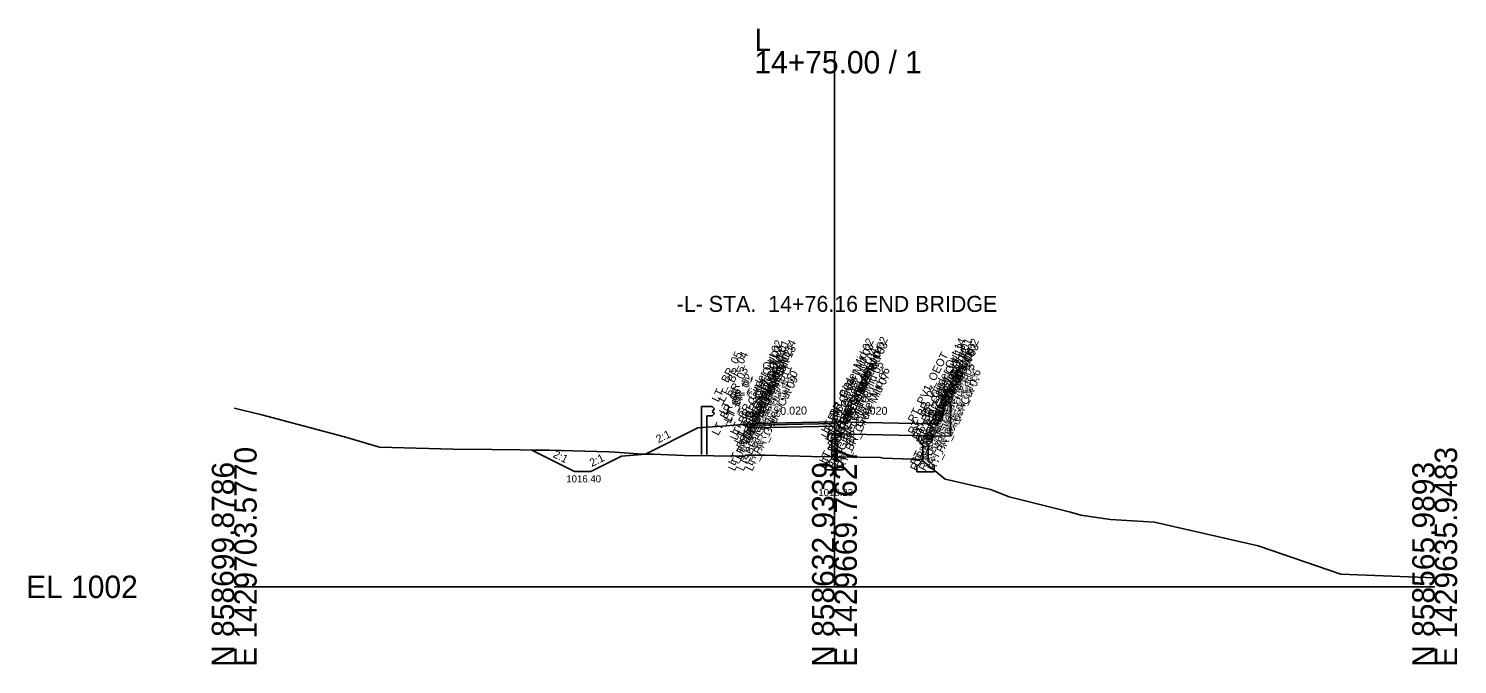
# Model space of a CAD drawing. Extents: x -26 to 153, y -10 to 13058.
# Drawn here: x -25.7 to 152.8, y 6490.3 to 6569.7 of the extents above; entities that cross this region are included whole.
import ezdxf

# ---------------------------------------------------------------- set-up
doc = ezdxf.new("R2010")
doc.units = 0
for name, color, linetype in [('Default', 7, 'Continuous'), ('Exist Cross Section Cell', 7, 'Continuous'), ('Exist XS Ground Line', 7, 'Continuous'), ('Old_Level_50', 7, 'Continuous'), ('Prop CMT Concrete Structures', 7, 'Continuous'), ('Prop CMT Ditch DDE', 7, 'Continuous'), ('Prop CMT Guardrail Graphics', 7, 'Continuous'), ('Prop CMT Pvmt Course 1', 7, 'Continuous'), ('Prop CMT Pvmt Course 2', 7, 'Continuous'), ('Prop CMT Pvmt Surface', 7, 'Continuous'), ('Prop CMT Pvmt Surface Shoulder', 7, 'Continuous'), ('Prop CMT Shld Paved Course 1', 7, 'Continuous'), ('Prop CMT Shld Paved Course 2', 7, 'Continuous'), ('Prop CMT Slope Grass', 7, 'Continuous'), ('Prop CMT Subgrade Daylight Point', 7, 'Continuous'), ('Prop CMT Subgrade Earthwork', 7, 'Continuous'), ('Prop XS Dump Level', 7, 'Continuous'), ('Prop XS SE Text', 7, 'Continuous'), ('Prop XS Side Slope Text', 7, 'Continuous'), ('Prop XSC Text', 7, 'Continuous')]:
    doc.layers.add(name, color=color, linetype=linetype)

msp = doc.modelspace()

# ---------------------------------------------------------------- linework, layer by layer
at = {"layer": 'Exist Cross Section Cell'}
for p, q in [((75, 6500), (75, 6566.93)), ((0, 6500), (75, 6500)), ((75, 6500), (150, 6500))]:
    msp.add_line(p, q, dxfattribs=at)
at = {"layer": 'Exist XS Ground Line'}
msp.add_lwpolyline([(0, 6522.31), (3.44, 6521.49), (13.79, 6518.72), (18.17, 6517.45), (27.35, 6517.18), (32.2, 6517.15), (39.36, 6517.05), (46.79, 6516.88), (47.56, 6516.84), (51.03, 6516.57), (52.33, 6516.56), (56.24, 6516.42), (59.9, 6516.38), (62.96, 6516.34), (63.78, 6516.33), (63.92, 6516.46), (66.35, 6516.43), (72.14, 6516.29), (75, 6516.23), (75.38, 6516.22), (80.77, 6516.15), (81.07, 6516.09), (85.84, 6515.89), (88.82, 6513.45), (94.51, 6512.15), (96.84, 6511.22), (104.48, 6509.34), (105.79, 6508.93), (109.51, 6508.39), (114.97, 6508.07), (127.95, 6505.12), (138.29, 6501.59), (146.77, 6501.25), (150, 6501.11)], dxfattribs=at)
at = {"layer": 'Old_Level_50'}
for p, q in [((37.18, 6517.08), (42.54, 6514.4)), ((48.39, 6516.33), (51.39, 6516.57)), ((51.39, 6516.57), (51.03, 6516.57)), ((44.54, 6514.4), (48.39, 6516.33)), ((42.54, 6514.4), (44.54, 6514.4))]:
    msp.add_line(p, q, dxfattribs=at)
msp.add_lwpolyline([(51.03, 6516.57), (47.56, 6516.84), (46.79, 6516.88), (39.36, 6517.05), (37.18, 6517.08)], dxfattribs=at)
at = {"layer": 'Prop CMT Concrete Structures'}
for points in [[(75, 6520.61), (85, 6520.41), (88, 6520.35), (88.01, 6520.6), (88.59, 6521.43), (88.76, 6523.01), (89.5, 6523.01), (89.5, 6518.82)], [(75, 6519.11), (75, 6520.61)], [(75, 6519.11), (75, 6520.61)], [(75, 6519.11), (74.17, 6519.09)], [(74.17, 6519.09), (74.17, 6518.44)], [(74.17, 6518.44), (74.67, 6517.94)], [(75, 6514.61), (75, 6519.11)], [(75, 6519.11), (75.83, 6519.09)], [(75, 6514.61), (75, 6519.11)], [(89.5, 6518.82), (85, 6518.91), (75, 6519.11)], [(75.83, 6518.44), (75.33, 6517.94)], [(75.83, 6519.09), (75.83, 6518.44)], [(85.54, 6518.9), (86.38, 6518.88), (87.21, 6518.86)], [(85.54, 6518.21), (85.54, 6518.9)], [(87.21, 6518.86), (87.21, 6518.21)], [(74.67, 6517.94), (74.67, 6516.02)], [(75.33, 6517.94), (75.33, 6516.02)], [(86.04, 6517.71), (85.54, 6518.21)], [(86.04, 6515.8), (86.04, 6517.71)], [(87.21, 6518.21), (86.71, 6517.71)], [(86.71, 6517.71), (86.71, 6515.8)], [(74.67, 6516.02), (73.92, 6515.27)], [(73.92, 6515.27), (73.92, 6514.61)], [(75.33, 6516.02), (76.08, 6515.27)], [(76.08, 6515.27), (76.08, 6514.61)], [(85.29, 6515.05), (86.04, 6515.8)], [(85.29, 6514.38), (85.29, 6515.05)], [(86.71, 6515.8), (87.46, 6515.05)], [(87.46, 6515.05), (87.46, 6514.38)], [(73.92, 6514.61), (75, 6514.61)], [(76.08, 6514.61), (75, 6514.61)], [(87.46, 6514.38), (86.38, 6514.38), (85.29, 6514.38)]]:
    msp.add_lwpolyline(points, dxfattribs=at)
at = {"layer": 'Prop CMT Ditch DDE'}
for p, q in [((42.54, 6514.4), (37.18, 6517.08)), ((51.39, 6516.57), (48.39, 6516.33)), ((44.54, 6514.4), (48.39, 6516.33)), ((44.54, 6514.4), (42.54, 6514.4))]:
    msp.add_line(p, q, dxfattribs=at)
at = {"layer": 'Prop CMT Guardrail Graphics'}
for points in [[(58.4, 6516.51), (58.4, 6522.51)], [(58.4, 6522.51), (59.73, 6522.51), (60, 6522.22)], [(60, 6522.22), (59.73, 6521.92)], [(59.73, 6521.92), (60, 6521.63)], [(60, 6521.63), (59.73, 6521.34), (59.06, 6521.34)], [(59.06, 6521.34), (59.06, 6516.51)]]:
    msp.add_lwpolyline(points, dxfattribs=at)
at = {"layer": 'Prop CMT Pvmt Course 1'}
for points in [[(75, 6520.61), (65, 6520.41)], [(65, 6520.41), (65, 6520.2)], [(65, 6520.2), (75, 6520.4)], [(75, 6520.4), (75, 6520.61)], [(75, 6520.4), (75, 6520.61)]]:
    msp.add_lwpolyline(points, dxfattribs=at)
msp.add_lwpolyline([(75, 6520.4), (75, 6520.48), (75, 6520.48), (75, 6520.4)], close=True, dxfattribs=at)
msp.add_lwpolyline([(75, 6520.4), (75, 6520.48), (75, 6520.48), (75, 6520.4)], close=True, dxfattribs=at)
at = {"layer": 'Prop CMT Pvmt Course 2'}
for points in [[(75, 6520.4), (65, 6520.2)], [(65, 6520.2), (65, 6519.87)], [(65, 6519.87), (75, 6520.07)], [(75, 6520.07), (75, 6520.4)], [(75, 6520.07), (75, 6520.4)]]:
    msp.add_lwpolyline(points, dxfattribs=at)
at = {"layer": 'Prop CMT Pvmt Surface'}
msp.add_lwpolyline([(75, 6520.61), (65, 6520.41)], dxfattribs=at)
at = {"layer": 'Prop CMT Pvmt Surface Shoulder'}
msp.add_lwpolyline([(65, 6520.41), (65, 6520.41)], dxfattribs=at)
at = {"layer": 'Prop CMT Shld Paved Course 1'}
for points in [[(65, 6520.41), (64.79, 6520.2)], [(64.79, 6520.2), (65, 6520.2)], [(65, 6520.41), (65, 6520.41)], [(65, 6520.2), (65, 6520.41)]]:
    msp.add_lwpolyline(points, dxfattribs=at)
at = {"layer": 'Prop CMT Shld Paved Course 2'}
for points in [[(64.79, 6520.2), (64.45, 6519.86)], [(65, 6520.2), (64.79, 6520.2)], [(64.79, 6520.2), (64.79, 6520.2)], [(65, 6519.87), (65, 6520.2)], [(64.45, 6519.86), (65, 6519.87)]]:
    msp.add_lwpolyline(points, dxfattribs=at)
at = {"layer": 'Prop CMT Slope Grass'}
for points in [[(60.95, 6520.08), (57.95, 6519.84)], [(65, 6520.41), (60.95, 6520.08)], [(57.95, 6519.84), (51.39, 6516.57)]]:
    msp.add_lwpolyline(points, dxfattribs=at)
at = {"layer": 'Prop CMT Subgrade Earthwork'}
for points in [[(64.45, 6519.86), (63.98, 6520.33)], [(75, 6520.07), (65, 6519.87)], [(65, 6519.87), (64.45, 6519.86)]]:
    msp.add_lwpolyline(points, dxfattribs=at)

# ---------------------------------------------------------------- texts
at = {"layer": 'Default'}
for s, height, p in [('1016.40', 0.9, (41.49, 6513.04)), ('-', 0.0001, (0, 6500))]:
    msp.add_text(s, height=height, dxfattribs=at).set_placement(p)
at = {"layer": 'Exist Cross Section Cell'}
for s, p in [('L', (65, 6566.93)), ('14+75.00 / 1', (65, 6564.13)), ('EL 1002', (-26, 6498.6))]:
    msp.add_text(s, height=2.8, dxfattribs=at).set_placement(p)
for s, p in [('E 1429703.5770', (2.8, 6490)), ('E 1429669.7627', (77.8, 6490)), ('E 1429635.9483', (152.8, 6490)), ('N 858699.8786', (0, 6490)), ('N 858632.9339', (75, 6490)), ('N 858565.9893', (150, 6490))]:
    msp.add_text(s, height=2.8, rotation=90, dxfattribs=at).set_placement(p)
at = {"layer": 'Prop CMT Subgrade Daylight Point'}
msp.add_text('1018.23', height=0.9, dxfattribs=at).set_placement((72.98, 6511.33))
at = {"layer": 'Prop XS Dump Level'}
for s, p in [('LT_BR_Girder Out 02', (62.79, 6518.86)), ('LT_BR_Girder Out 14', (64.46, 6518.9)), ('LT_BR_Girder Mid 02', (74.17, 6519.09)), ('RT_BR_Girder Mid 02', (75.83, 6519.09)), ('RT_BR_Girder Out 14', (85.54, 6518.9)), ('RT_BR_Girder Out 01', (86.38, 6518.88)), ('RT_BR_Girder Out 02', (87.21, 6518.86)), ('LT_ BR_05', (60.5, 6523.01)), ('LT_ BR_04', (61.24, 6523.01)), ('LT_BR_Girder Out 03', (62.79, 6518.21)), ('LT_BR_Girder Out 04', (63.29, 6517.71)), ('LT_BR_Girder Out 01', (63.62, 6518.88)), ('LT_BR_Girder Out 12', (63.96, 6517.71)), ('LT_BR_Girder Out 13', (64.46, 6518.21)), ('LT_PV1_OEOT', (65, 6520.41)), ('LT_BR_Girder Mid 03', (74.17, 6518.44)), ('LT_BR_Girder Mid 04', (74.67, 6517.94)), ('RT_BR_Girder Mid 04', (75.33, 6517.94)), ('RT_BR_Girder Mid 03', (75.83, 6518.44)), ('RT_PV1_OEOT', (85, 6520.41)), ('RT_BR_Girder Out 13', (85.54, 6518.21)), ('RT_BR_Girder Out 12', (86.04, 6517.71)), ('RT_BR_Girder Out 04', (86.71, 6517.71)), ('RT_BR_Girder Out 03', (87.21, 6518.21)), ('RT_ BR_04', (88.76, 6523.01)), ('RT_ BR_05', (89.5, 6523.01)), ('LT_BR_03', (61.41, 6521.43)), ('LT_BR_Girder Out 05', (63.29, 6515.8)), ('LT_BR_Girder Out 11', (63.96, 6515.8)), ('LT_BR_Girder Mid 06', (73.92, 6515.27)), ('LT_BR_Girder Mid 05', (74.67, 6516.02)), ('RT_BR_Girder Mid 05', (75.33, 6516.02)), ('RT_BR_Girder Mid 06', (76.08, 6515.27)), ('RT_BR_Girder Out 10', (85.29, 6515.05)), ('RT_BR_Girder Out 11', (86.04, 6515.8)), ('RT_BR_Girder Out 05', (86.71, 6515.8)), ('RT_BR_Girder Out 06', (87.46, 6515.05)), ('RT_BR_03', (88.59, 6521.43)), ('LT_BR_02', (61.99, 6520.6)), ('LT_BR_01', (62, 6520.35)), ('LT_BR_Girder Out 06', (62.54, 6515.05)), ('LT_BR_Girder Out 07', (62.54, 6514.38)), ('LT_BR_Girder Out 08', (63.62, 6514.38)), ('LT_BR_Girder Out 10', (64.71, 6515.05)), ('LT_BR_Girder Out 09', (64.71, 6514.38)), ('LT_BR_Girder Mid 07', (73.92, 6514.61)), ('PV1_PGL', (75, 6520.61)), ('RT_BR_Girder Mid 07', (76.08, 6514.61)), ('RT_BR_Girder Out 09', (85.29, 6514.38)), ('RT_BR_Girder Out 08', (86.38, 6514.38)), ('RT_BR_Girder Out 07', (87.46, 6514.38)), ('RT_BR_01', (88, 6520.35)), ('RT_BR_02', (88.01, 6520.6)), ('LT_BR_06', (60.5, 6518.82)), ('LT_BR_07', (65, 6518.91)), ('BR_Girder Mid 08', (75, 6514.61)), ('BR_PGL', (75, 6519.11)), ('RT_BR_07', (85, 6518.91)), ('RT_BR_06', (89.5, 6518.82))]:
    msp.add_text(s, height=1, rotation=63.5833, dxfattribs=at).set_placement(p)
at = {"layer": 'Prop XS SE Text'}
for rotation, p in [(1.1458, (68.23, 6521.47)), (358.8542, (78.27, 6521.54))]:
    msp.add_text('0.020', height=1, rotation=rotation, dxfattribs=at).set_placement(p)
at = {"layer": 'Prop XS Side Slope Text'}
for rotation, p in [(26.5651, (53, 6517.92)), (333.4349, (39.74, 6516.24)), (26.5651, (44.7, 6514.96))]:
    msp.add_text('2:1', height=1, rotation=rotation, dxfattribs=at).set_placement(p)
at = {"layer": 'Prop XSC Text'}
msp.add_text('-L- STA.  14+76.16 END BRIDGE', height=2, dxfattribs=at).set_placement((55.28, 6534.34))

doc.saveas('drawing.dxf')
